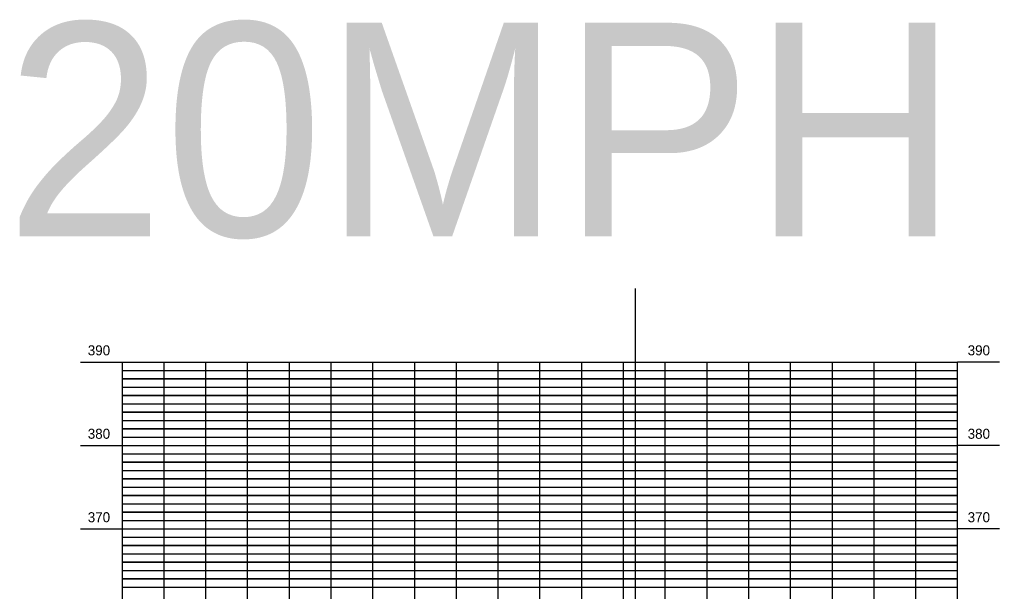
# Model space of a CAD drawing. Extents: x 1195880 to 1289360, y 2059330 to 2086925.
# Drawn here: x 1197002 to 1197589, y 2062687 to 2063029 of the extents above; entities that cross this region are included whole.
import ezdxf

# ---------------------------------------------------------------- set-up
doc = ezdxf.new("R2010")
doc.units = 0
for name, color, linetype in [('Default', 7, 'Continuous'), ('Grid', 7, 'Continuous'), ('Grid Lables', 7, 'Continuous')]:
    doc.layers.add(name, color=color, linetype=linetype)

msp = doc.modelspace()

# ---------------------------------------------------------------- linework, layer by layer
at = {"layer": 'Default'}
msp.add_line((1197371.02, 2062224.28), (1197371.02, 2062868.37), dxfattribs=at)
at = {"layer": 'Grid'}
for p, q in [((1197038.84, 2062824.28), (1197063.84, 2062824.28)), ((1197038.84, 2062824.28), (1197063.84, 2062824.28)), ((1197063.84, 2062224.28), (1197063.84, 2062824.28)), ((1197063.84, 2062824.28), (1197563.84, 2062824.28)), ((1197063.84, 2062824.28), (1197563.84, 2062824.28)), ((1197088.84, 2062224.28), (1197088.84, 2062824.28)), ((1197113.84, 2062224.28), (1197113.84, 2062824.28)), ((1197138.84, 2062224.28), (1197138.84, 2062824.28)), ((1197163.84, 2062224.28), (1197163.84, 2062824.28)), ((1197188.84, 2062224.28), (1197188.84, 2062824.28)), ((1197213.84, 2062224.28), (1197213.84, 2062824.28)), ((1197238.84, 2062224.28), (1197238.84, 2062824.28)), ((1197263.84, 2062224.28), (1197263.84, 2062824.28)), ((1197288.84, 2062224.28), (1197288.84, 2062824.28)), ((1197313.84, 2062224.28), (1197313.84, 2062824.28)), ((1197338.84, 2062224.28), (1197338.84, 2062824.28)), ((1197363.84, 2062224.28), (1197363.84, 2062824.28)), ((1197388.84, 2062224.28), (1197388.84, 2062824.28)), ((1197413.84, 2062224.28), (1197413.84, 2062824.28)), ((1197438.84, 2062224.28), (1197438.84, 2062824.28)), ((1197463.84, 2062224.28), (1197463.84, 2062824.28)), ((1197488.84, 2062224.28), (1197488.84, 2062824.28)), ((1197513.84, 2062224.28), (1197513.84, 2062824.28)), ((1197538.84, 2062224.28), (1197538.84, 2062824.28)), ((1197563.84, 2062224.28), (1197563.84, 2062824.28)), ((1197588.84, 2062824.28), (1197563.84, 2062824.28)), ((1197588.84, 2062824.28), (1197563.84, 2062824.28)), ((1197063.84, 2062819.28), (1197066.84, 2062819.28)), ((1197063.84, 2062819.28), (1197563.84, 2062819.28)), ((1197063.84, 2062814.28), (1197066.84, 2062814.28)), ((1197063.84, 2062814.28), (1197563.84, 2062814.28)), ((1197563.84, 2062814.28), (1197063.84, 2062814.28)), ((1197063.84, 2062809.28), (1197066.84, 2062809.28)), ((1197063.84, 2062809.28), (1197563.84, 2062809.28)), ((1197063.84, 2062804.28), (1197066.84, 2062804.28)), ((1197063.84, 2062804.28), (1197563.84, 2062804.28)), ((1197563.84, 2062804.28), (1197063.84, 2062804.28)), ((1197063.84, 2062799.28), (1197066.84, 2062799.28)), ((1197063.84, 2062799.28), (1197563.84, 2062799.28)), ((1197063.84, 2062794.28), (1197066.84, 2062794.28)), ((1197063.84, 2062794.28), (1197563.84, 2062794.28)), ((1197563.84, 2062794.28), (1197063.84, 2062794.28)), ((1197063.84, 2062789.28), (1197066.84, 2062789.28)), ((1197063.84, 2062789.28), (1197563.84, 2062789.28)), ((1197063.84, 2062784.28), (1197066.84, 2062784.28)), ((1197063.84, 2062784.28), (1197563.84, 2062784.28)), ((1197563.84, 2062784.28), (1197063.84, 2062784.28)), ((1197063.84, 2062779.28), (1197066.84, 2062779.28)), ((1197063.84, 2062779.28), (1197563.84, 2062779.28)), ((1197038.84, 2062774.28), (1197063.84, 2062774.28)), ((1197063.84, 2062774.28), (1197563.84, 2062774.28)), ((1197063.84, 2062769.28), (1197066.84, 2062769.28)), ((1197063.84, 2062769.28), (1197563.84, 2062769.28)), ((1197588.84, 2062774.28), (1197563.84, 2062774.28)), ((1197063.84, 2062764.28), (1197066.84, 2062764.28)), ((1197063.84, 2062764.28), (1197563.84, 2062764.28)), ((1197563.84, 2062764.28), (1197063.84, 2062764.28)), ((1197063.84, 2062759.28), (1197066.84, 2062759.28)), ((1197063.84, 2062759.28), (1197563.84, 2062759.28)), ((1197063.84, 2062754.28), (1197066.84, 2062754.28)), ((1197063.84, 2062754.28), (1197563.84, 2062754.28)), ((1197563.84, 2062754.28), (1197063.84, 2062754.28)), ((1197063.84, 2062749.28), (1197066.84, 2062749.28)), ((1197063.84, 2062749.28), (1197563.84, 2062749.28)), ((1197063.84, 2062744.28), (1197066.84, 2062744.28)), ((1197063.84, 2062744.28), (1197563.84, 2062744.28)), ((1197563.84, 2062744.28), (1197063.84, 2062744.28)), ((1197063.84, 2062739.28), (1197066.84, 2062739.28)), ((1197063.84, 2062739.28), (1197563.84, 2062739.28)), ((1197063.84, 2062734.28), (1197066.84, 2062734.28)), ((1197063.84, 2062734.28), (1197563.84, 2062734.28)), ((1197563.84, 2062734.28), (1197063.84, 2062734.28)), ((1197063.84, 2062729.28), (1197066.84, 2062729.28)), ((1197063.84, 2062729.28), (1197563.84, 2062729.28)), ((1197038.84, 2062724.28), (1197063.84, 2062724.28)), ((1197063.84, 2062724.28), (1197563.84, 2062724.28)), ((1197588.84, 2062724.28), (1197563.84, 2062724.28)), ((1197063.84, 2062719.28), (1197066.84, 2062719.28)), ((1197063.84, 2062719.28), (1197563.84, 2062719.28)), ((1197063.84, 2062714.28), (1197066.84, 2062714.28)), ((1197063.84, 2062714.28), (1197563.84, 2062714.28)), ((1197563.84, 2062714.28), (1197063.84, 2062714.28)), ((1197063.84, 2062709.28), (1197066.84, 2062709.28)), ((1197063.84, 2062709.28), (1197563.84, 2062709.28)), ((1197063.84, 2062704.28), (1197066.84, 2062704.28)), ((1197063.84, 2062704.28), (1197563.84, 2062704.28)), ((1197563.84, 2062704.28), (1197063.84, 2062704.28)), ((1197063.84, 2062699.28), (1197066.84, 2062699.28)), ((1197063.84, 2062699.28), (1197563.84, 2062699.28)), ((1197063.84, 2062694.28), (1197066.84, 2062694.28)), ((1197063.84, 2062694.28), (1197563.84, 2062694.28)), ((1197563.84, 2062694.28), (1197063.84, 2062694.28)), ((1197063.84, 2062689.28), (1197066.84, 2062689.28)), ((1197063.84, 2062689.28), (1197563.84, 2062689.28))]:
    msp.add_line(p, q, dxfattribs=at)

# ---------------------------------------------------------------- texts
at = {"layer": 'Default'}
msp.add_text('20MPH', height=128, rotation=360, dxfattribs=at).set_placement((1196993.73, 2062899.55))
at = {"layer": 'Grid Lables'}
for s, p in [('390', (1197043.15, 2062828.28)), ('390', (1197043.15, 2062828.28)), ('390', (1197569.84, 2062828.28)), ('390', (1197569.84, 2062828.28)), ('380', (1197043.15, 2062778.28)), ('380', (1197569.84, 2062778.28)), ('370', (1197043.15, 2062728.28)), ('370', (1197569.84, 2062728.28))]:
    msp.add_text(s, height=6, rotation=360, dxfattribs=at).set_placement(p)

doc.saveas('drawing.dxf')
